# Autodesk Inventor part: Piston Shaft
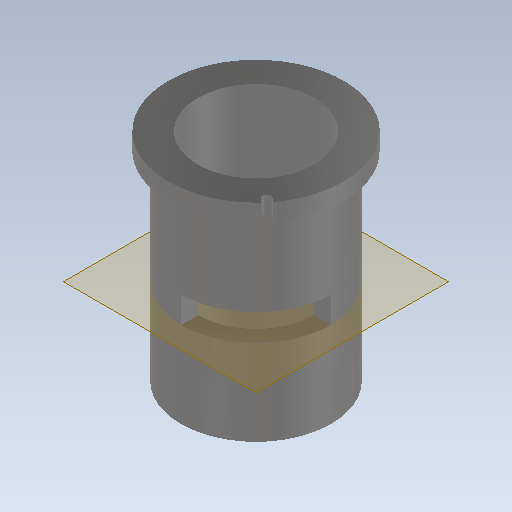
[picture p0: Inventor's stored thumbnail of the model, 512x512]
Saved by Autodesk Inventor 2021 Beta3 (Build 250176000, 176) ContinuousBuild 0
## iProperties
Created: 2012-08
Part Number: Piston Shaft
Material: Stainless Steel
Document SubType Name: Modeling
Designer: John
Density: 1 g/cm^3
Appearance: Semi-Polished
Author: John
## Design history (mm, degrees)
sketch "Sketch1"
  geometry: C1 r 10.541 at (0, 0); 1 further point
  constraints: 1 centre point, 1 coincident
  dimensions: "d2" = 21.082 diameter of C1
extrude "Extrusion1" new body sketch "Sketch1" distance "d0" = 2.032; taper "d1" = 0 deg
sketch "Sketch2"
  geometry: C1 r 10.541 at (0, 0) reference; C2 r 9.017 at (0, 0)
  constraints: 1 centre point, 1 coincident
  dimensions: "d4" = 18.034 diameter of C2
extrude "Extrusion2" join sketch "Sketch2" distance "d5" = 24.003; taper "d6" = 0 deg
hole "Hole1" diameter "d9" = 13.97; stored, may be unused: countersink angle "d13" = 82 deg, drill point angle "d15" = 118 deg; dims "d7" = 25.4, "d8" = 25.4, "d10" = 19.05, "d11" = 9.525, "d12" = 6.35, "d14" = 25.4
workplane "Work Plane1"
sketch "Sketch3"
  geometry: L1 (0, 0)-(9.017, 0); L2 (9.017, 0)-(9.017, -9.017); L3 (9.017, -9.017)-(0, -9.017); L4 (0, -9.017)-(0, 0)
  constraints: 8 end point, 2 parallel, 1 horizontal, 1 perpendicular
  dimensions: "d17" = 9.017 distance of L2.end L3.end; "d18" = 9.017 distance of L1.end L2.end
extrude "Extrusion3" cut sketch "Sketch3" distance "d19" = 3.175; taper "d20" = 0 deg
sketch "Sketch4"
  geometry: L1 (7.62, -6.35)-(0, 0); L2 (7.945, -5.96)-(8.414, -6.35); L3 (7.295, -6.74)-(7.763, -7.131); A1 r 10.541 centre (0, 0) between (8.414, -6.35) and (7.763, -7.131) reference; A2 r 0.508 centre (7.62, -6.35) between (7.945, -5.96) and (7.295, -6.74)
  constraints: 6 end point, 4 point on circle, 2 parallel, 2 tangent, 1 centre point
  dimensions: "d21" = 1.016 diameter of A2; "d22" = 6.35 vertical distance of L1.end L1.start; "d23" = 7.62 horizontal distance of L1.end L1.start
extrude "Extrusion4" cut sketch "Sketch4" stored distance "d24" = 3.175; taper "d25" = 0 deg
body "Solid1"
other parameters: "d16" = -15.6972
